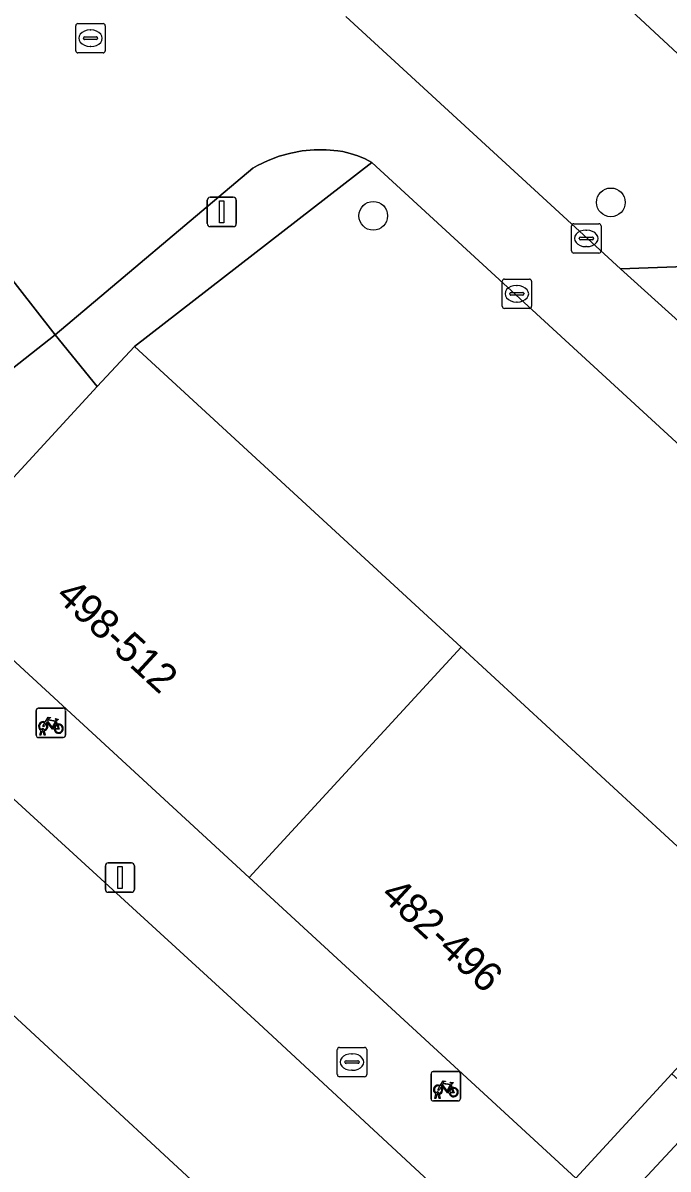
# Model space of a CAD drawing. Extents: x 159217 to 160349, y 381246 to 382172.
# Drawn here: x 159638.89 to 159660.85, y 381556.67 to 381595.69 of the extents above; entities that cross this region are included whole.
import ezdxf

# ---------------------------------------------------------------- set-up
doc = ezdxf.new("R2010")
doc.units = 0
for name, color, linetype in [('IMGEO_Boom', 7, 'Continuous'), ('IMGEO_Brandkraan', 7, 'Continuous'), ('IMGEO_Fietsenrek', 7, 'Continuous'), ('IMGEO_Groenvoorziening', 7, 'Continuous'), ('IMGEO_Kolk', 7, 'Continuous'), ('IMGEO_Lichtmast', 7, 'Continuous'), ('IMGEO_Pand', 7, 'Continuous'), ('IMGEO_Pand_nummerreeks', 7, 'Continuous'), ('IMGEO_Parkeervlak_open', 7, 'Continuous'), ('IMGEO_Rijbaan_lokaal_open', 7, 'Continuous'), ('IMGEO_Voetpad_open', 7, 'Continuous')]:
    doc.layers.add(name, color=color, linetype=linetype)

msp = doc.modelspace()

# ---------------------------------------------------------------- linework, layer by layer
at = {"layer": 'IMGEO_Boom'}
for centre in [(159658.907, 381589.584), (159650.817, 381589.128)]:
    msp.add_circle(centre, 0.489, dxfattribs=at)
at = {"layer": 'IMGEO_Brandkraan'}
for p, q in [((159649.594, 381559.889), (159649.594, 381560.741)), ((159649.669, 381560.815), (159650.521, 381560.815)), ((159650.082, 381560.595), (159650.107, 381560.595)), ((159650.595, 381560.741), (159650.595, 381559.889)), ((159649.853, 381560.309), (159649.853, 381560.321)), ((159650.291, 381560.272), (159649.893, 381560.272)), ((159649.896, 381560.358), (159650.294, 381560.358)), ((159650.337, 381560.321), (159650.337, 381560.309)), ((159650.521, 381559.815), (159649.669, 381559.815)), ((159650.105, 381560.035), (159650.08, 381560.035))]:
    msp.add_line(p, q, dxfattribs=at)
for points in [[(159649.594, 381559.889), (159649.594, 381560.741)], [(159649.669, 381560.815), (159650.521, 381560.815)], [(159650.595, 381560.741), (159650.595, 381559.889)], [(159650.521, 381559.815), (159649.669, 381559.815)]]:
    msp.add_lwpolyline(points, dxfattribs=at)
for centre, radius, start, end in [((159649.671, 381560.739), 0.0765, 91.552, 178.448), ((159649.671, 381560.739), 0.0765, 91.552, 178.448), ((159650.519, 381560.739), 0.0765, 1.552, 88.448), ((159650.519, 381560.739), 0.0765, 1.552, 88.448), ((159649.893, 381560.318), 0.0403, 85.8775, 175.7526), ((159649.89, 381560.308), 0.0366, 178.938, 274.7102), ((159650.294, 381560.315), 0.043, 264.8664, 352.4533), ((159650.298, 381560.32), 0.0386, 1.7309, 96.639), ((159649.671, 381559.891), 0.0765, 181.552, 268.448), ((159649.671, 381559.891), 0.0765, 181.552, 268.448), ((159650.519, 381559.891), 0.0765, 271.552, 358.448), ((159650.519, 381559.891), 0.0765, 271.552, 358.448)]:
    msp.add_arc(centre, radius, start, end, dxfattribs=at)
for centre, major_axis, ratio, start_param, end_param in [((159650.081, 381560.315), (-0.387, 0.002), 0.722429, 4.712389, 7.853982), ((159650.106, 381560.315), (-0.39, 0.002), 0.717154, 1.570796, 4.712389)]:
    msp.add_ellipse(centre, major_axis=major_axis, ratio=ratio, start_param=start_param, end_param=end_param, dxfattribs=at)
at = {"layer": 'IMGEO_Fietsenrek'}
for p, q in [((159639.341, 381571.44), (159639.341, 381572.281)), ((159639.341, 381572.281), (159639.341, 381571.44)), ((159639.416, 381572.365), (159640.257, 381572.365)), ((159640.257, 381572.365), (159639.416, 381572.365)), ((159640.341, 381572.29), (159640.341, 381571.449)), ((159640.341, 381571.449), (159640.341, 381572.29)), ((159640.028, 381571.914), (159640.064, 381571.819)), ((159640.266, 381571.365), (159639.425, 381571.365)), ((159639.425, 381571.365), (159640.266, 381571.365)), ((159639.468, 381571.449), (159639.507, 381571.609)), ((159639.502, 381571.449), (159639.468, 381571.449)), ((159639.537, 381571.597), (159639.502, 381571.449)), ((159639.579, 381571.621), (159639.578, 381571.625)), ((159639.62, 381571.449), (159639.586, 381571.591)), ((159639.61, 381571.632), (159639.611, 381571.625)), ((159639.618, 381571.595), (159639.653, 381571.449)), ((159639.653, 381571.449), (159639.62, 381571.449)), ((159652.785, 381559.065), (159652.785, 381559.906)), ((159652.785, 381559.906), (159652.785, 381559.065)), ((159652.86, 381559.99), (159653.701, 381559.99)), ((159653.701, 381559.99), (159652.86, 381559.99)), ((159653.785, 381559.915), (159653.785, 381559.074)), ((159653.785, 381559.074), (159653.785, 381559.915)), ((159653.472, 381559.539), (159653.508, 381559.444)), ((159653.71, 381558.99), (159652.869, 381558.99)), ((159652.869, 381558.99), (159653.71, 381558.99)), ((159652.912, 381559.074), (159652.951, 381559.234)), ((159652.946, 381559.074), (159652.912, 381559.074)), ((159652.981, 381559.222), (159652.946, 381559.074)), ((159653.023, 381559.246), (159653.022, 381559.25)), ((159653.064, 381559.074), (159653.03, 381559.216)), ((159653.054, 381559.257), (159653.055, 381559.25)), ((159653.062, 381559.22), (159653.097, 381559.074)), ((159653.097, 381559.074), (159653.064, 381559.074))]:
    msp.add_line(p, q, dxfattribs=at)
for points in [[(159639.675, 381571.839), (159639.623, 381571.749), (159639.583, 381571.724), (159639.584, 381571.771), (159639.639, 381571.865)], [(159639.654, 381571.891), (159639.749, 381572.055), (159639.835, 381572.041), (159639.837, 381572.032), (159639.781, 381572.021), (159639.754, 381571.976), (159640.01, 381571.935)], [(159639.95, 381571.647), (159639.9, 381571.647), (159639.709, 381571.898), (159639.69, 381571.866)], [(159639.997, 381571.91), (159639.74, 381571.951), (159639.723, 381571.922), (159639.89, 381571.702), (159639.997, 381571.91)], [(159640.045, 381571.812), (159640.015, 381571.889), (159639.906, 381571.671), (159639.949, 381571.671)], [(159639.979, 381571.671), (159640.099, 381571.67), (159640.055, 381571.784)], [(159640.075, 381571.791), (159640.13, 381571.646), (159639.98, 381571.646)], [(159640.01, 381571.935), (159640.035, 381571.984), (159640.029, 381571.988), (159640.006, 381571.992), (159639.994, 381571.999), (159639.993, 381572.002), (159639.995, 381572.007), (159640.09, 381571.992), (159640.092, 381571.982), (159640.082, 381571.969), (159640.07, 381571.963), (159640.056, 381571.969), (159640.028, 381571.914)], [(159653.098, 381559.516), (159653.193, 381559.68), (159653.279, 381559.666), (159653.281, 381559.657), (159653.225, 381559.646), (159653.198, 381559.601), (159653.454, 381559.56)], [(159653.119, 381559.464), (159653.067, 381559.374), (159653.027, 381559.349), (159653.028, 381559.396), (159653.083, 381559.49)], [(159653.394, 381559.272), (159653.344, 381559.272), (159653.153, 381559.523), (159653.134, 381559.491)], [(159653.441, 381559.535), (159653.184, 381559.576), (159653.167, 381559.547), (159653.334, 381559.327), (159653.441, 381559.535)], [(159653.489, 381559.437), (159653.459, 381559.514), (159653.35, 381559.296), (159653.393, 381559.296)], [(159653.423, 381559.296), (159653.543, 381559.295), (159653.499, 381559.409)], [(159653.519, 381559.416), (159653.574, 381559.271), (159653.424, 381559.271)], [(159653.454, 381559.56), (159653.479, 381559.609), (159653.473, 381559.613), (159653.45, 381559.617), (159653.438, 381559.624), (159653.437, 381559.627), (159653.439, 381559.632), (159653.534, 381559.617), (159653.536, 381559.607), (159653.526, 381559.594), (159653.514, 381559.588), (159653.5, 381559.594), (159653.472, 381559.539)]]:
    msp.add_lwpolyline(points, dxfattribs=at)
for centre, radius, start, end in [((159639.419, 381572.287), 0.0779, 92.4484, 184.2845), ((159639.419, 381572.287), 0.0779, 92.4484, 184.2845), ((159640.263, 381572.287), 0.0779, 2.4484, 94.2845), ((159640.263, 381572.287), 0.0779, 2.4484, 94.2845), ((159639.581, 381571.75), 0.159, 62.6766, 242.1369), ((159639.581, 381571.75), 0.129, 63.3192, 238.903), ((159639.581, 381571.75), 0.129, 283.6043, 43.4302), ((159639.581, 381571.75), 0.159, 283.5766, 46.6042), ((159640.108, 381571.666), 0.159, 113.3408, 178.3217), ((159640.108, 381571.666), 0.159, 187.0065, 105.7708), ((159640.108, 381571.666), 0.129, 113.923, 177.9556), ((159640.108, 381571.666), 0.129, 188.6715, 104.5883), ((159639.419, 381571.443), 0.0779, 182.4484, 274.2845), ((159639.419, 381571.443), 0.0779, 182.4484, 274.2845), ((159639.561, 381571.621), 0.0499, 12.8025, 158.6934), ((159639.581, 381571.75), 0.159, 253.9967, 271.7867), ((159639.561, 381571.621), 0.0174, 12.8025, 163.4502), ((159639.581, 381571.75), 0.129, 253.415, 269.0204), ((159640.263, 381571.443), 0.0779, 272.4484, 4.2845), ((159640.263, 381571.443), 0.0779, 272.4484, 4.2845), ((159652.863, 381559.912), 0.0779, 92.4484, 184.2845), ((159652.863, 381559.912), 0.0779, 92.4484, 184.2845), ((159653.707, 381559.912), 0.0779, 2.4484, 94.2845), ((159653.707, 381559.912), 0.0779, 2.4484, 94.2845), ((159653.025, 381559.375), 0.159, 62.6766, 242.1369), ((159653.025, 381559.375), 0.129, 63.3192, 238.903), ((159653.005, 381559.246), 0.0499, 12.8025, 158.6934), ((159653.005, 381559.246), 0.0174, 12.8025, 163.4502), ((159653.025, 381559.375), 0.129, 283.6043, 43.4302), ((159653.025, 381559.375), 0.159, 283.5766, 46.6042), ((159653.552, 381559.291), 0.159, 113.3408, 178.3217), ((159653.552, 381559.291), 0.159, 187.0065, 105.7708), ((159653.552, 381559.291), 0.129, 113.923, 177.9556), ((159653.552, 381559.291), 0.129, 188.6715, 104.5883), ((159652.863, 381559.068), 0.0779, 182.4484, 274.2845), ((159652.863, 381559.068), 0.0779, 182.4484, 274.2845), ((159653.025, 381559.375), 0.159, 253.9967, 271.7867), ((159653.025, 381559.375), 0.129, 253.415, 269.0204), ((159653.707, 381559.068), 0.0779, 272.4484, 4.2845), ((159653.707, 381559.068), 0.0779, 272.4484, 4.2845)]:
    msp.add_arc(centre, radius, start, end, dxfattribs=at)
at = {"layer": 'IMGEO_Groenvoorziening'}
msp.add_lwpolyline([(159692.005, 381604.643), (159690.074, 381606.457), (159682.249, 381613.809), (159680.462, 381615.488), (159678.112, 381617.696), (159666.889, 381608.847), (159664.757, 381607.166), (159661.453, 381604.561), (159655.531, 381599.891), (159667.442, 381588.844), (159673.929, 381582.827), (159675.769, 381581.12), (159687.565, 381570.179), (159706.244, 381585.938), (159705.893, 381586.316), (159707.664, 381587.959), (159708.044, 381587.55), (159709.165, 381588.521), (159704.338, 381593.056)], close=True, dxfattribs=at)
for points in [[(159649.883, 381595.917), (159652.392, 381593.608), (159653.239, 381592.829), (159659.239, 381587.321), (159666.781, 381587.598), (159666.437, 381587.895), (159667.442, 381588.844), (159655.531, 381599.891)], [(159650.773, 381590.94), (159642.684, 381584.683), (159653.807, 381574.44), (159664.922, 381564.205), (159663.33, 381562.473), (159665.149, 381560.892), (159665.707, 381560.407), (159663.314, 381557.831), (159662.858, 381558.237), (159662.123, 381557.38), (159661.529, 381557.926), (159658.33, 381554.491), (159662.979, 381550.231), (159679.309, 381562.818)], [(159677.507, 381566.366), (159650.773, 381590.94)]]:
    msp.add_lwpolyline(points, dxfattribs=at)
at = {"layer": 'IMGEO_Kolk'}
for p, q in [((159640.691, 381594.748), (159640.691, 381595.6)), ((159640.766, 381595.674), (159641.618, 381595.674)), ((159641.692, 381595.6), (159641.692, 381594.748)), ((159640.95, 381595.168), (159640.95, 381595.18)), ((159640.993, 381595.217), (159641.391, 381595.217)), ((159641.179, 381595.454), (159641.204, 381595.454)), ((159641.434, 381595.18), (159641.434, 381595.168)), ((159641.388, 381595.131), (159640.99, 381595.131)), ((159641.202, 381594.894), (159641.177, 381594.894)), ((159641.618, 381594.674), (159640.766, 381594.674)), ((159657.571, 381587.931), (159657.571, 381588.783)), ((159657.646, 381588.857), (159658.498, 381588.857)), ((159658.059, 381588.637), (159658.084, 381588.637)), ((159658.572, 381588.783), (159658.572, 381587.931)), ((159657.83, 381588.351), (159657.83, 381588.363)), ((159658.268, 381588.314), (159657.87, 381588.314)), ((159657.873, 381588.4), (159658.271, 381588.4)), ((159658.314, 381588.363), (159658.314, 381588.351)), ((159658.498, 381587.857), (159657.646, 381587.857)), ((159658.082, 381588.077), (159658.057, 381588.077)), ((159655.281, 381586.972), (159656.133, 381586.972)), ((159655.206, 381586.046), (159655.206, 381586.898)), ((159655.694, 381586.752), (159655.719, 381586.752)), ((159656.207, 381586.898), (159656.207, 381586.046)), ((159655.465, 381586.466), (159655.465, 381586.478)), ((159655.903, 381586.429), (159655.505, 381586.429)), ((159655.508, 381586.515), (159655.906, 381586.515)), ((159655.717, 381586.192), (159655.692, 381586.192)), ((159655.949, 381586.478), (159655.949, 381586.466)), ((159656.133, 381585.972), (159655.281, 381585.972))]:
    msp.add_line(p, q, dxfattribs=at)
for points in [[(159640.691, 381594.748), (159640.691, 381595.6)], [(159640.766, 381595.674), (159641.618, 381595.674)], [(159641.692, 381595.6), (159641.692, 381594.748)], [(159641.618, 381594.674), (159640.766, 381594.674)], [(159657.571, 381587.931), (159657.571, 381588.783)], [(159657.646, 381588.857), (159658.498, 381588.857)], [(159658.572, 381588.783), (159658.572, 381587.931)], [(159658.498, 381587.857), (159657.646, 381587.857)], [(159655.281, 381586.972), (159656.133, 381586.972)], [(159655.206, 381586.046), (159655.206, 381586.898)], [(159656.207, 381586.898), (159656.207, 381586.046)], [(159656.133, 381585.972), (159655.281, 381585.972)]]:
    msp.add_lwpolyline(points, dxfattribs=at)
for centre, radius, start, end in [((159640.768, 381595.598), 0.0765, 91.552, 178.448), ((159640.768, 381595.598), 0.0765, 91.552, 178.448), ((159641.616, 381595.598), 0.0765, 1.552, 88.448), ((159641.616, 381595.598), 0.0765, 1.552, 88.448), ((159640.99, 381595.177), 0.0403, 85.8775, 175.7526), ((159640.987, 381595.167), 0.0366, 178.938, 274.7102), ((159641.391, 381595.174), 0.043, 264.8664, 352.4533), ((159641.395, 381595.179), 0.0386, 1.7309, 96.639), ((159640.768, 381594.75), 0.0765, 181.552, 268.448), ((159640.768, 381594.75), 0.0765, 181.552, 268.448), ((159641.616, 381594.75), 0.0765, 271.552, 358.448), ((159641.616, 381594.75), 0.0765, 271.552, 358.448), ((159657.648, 381588.781), 0.0765, 91.552, 178.448), ((159657.648, 381588.781), 0.0765, 91.552, 178.448), ((159658.496, 381588.781), 0.0765, 1.552, 88.448), ((159658.496, 381588.781), 0.0765, 1.552, 88.448), ((159657.87, 381588.36), 0.0403, 85.8775, 175.7526), ((159657.867, 381588.35), 0.0366, 178.938, 274.7102), ((159658.271, 381588.357), 0.043, 264.8664, 352.4533), ((159658.275, 381588.362), 0.0386, 1.7309, 96.639), ((159657.648, 381587.933), 0.0765, 181.552, 268.448), ((159657.648, 381587.933), 0.0765, 181.552, 268.448), ((159658.496, 381587.933), 0.0765, 271.552, 358.448), ((159658.496, 381587.933), 0.0765, 271.552, 358.448), ((159655.283, 381586.896), 0.0765, 91.552, 178.448), ((159655.283, 381586.896), 0.0765, 91.552, 178.448), ((159656.131, 381586.896), 0.0765, 1.552, 88.448), ((159656.131, 381586.896), 0.0765, 1.552, 88.448), ((159655.505, 381586.475), 0.0403, 85.8775, 175.7526), ((159655.502, 381586.465), 0.0366, 178.938, 274.7102), ((159655.906, 381586.472), 0.043, 264.8664, 352.4533), ((159655.91, 381586.477), 0.0386, 1.7309, 96.639), ((159655.283, 381586.048), 0.0765, 181.552, 268.448), ((159655.283, 381586.048), 0.0765, 181.552, 268.448), ((159656.131, 381586.048), 0.0765, 271.552, 358.448), ((159656.131, 381586.048), 0.0765, 271.552, 358.448)]:
    msp.add_arc(centre, radius, start, end, dxfattribs=at)
for centre, major_axis, ratio, start_param, end_param in [((159641.178, 381595.174), (-0.387, 0.002), 0.722429, 4.712389, 7.853982), ((159641.203, 381595.174), (-0.39, 0.002), 0.717154, 1.570796, 4.712389), ((159658.058, 381588.357), (-0.387, 0.002), 0.722429, 4.712389, 7.853982), ((159658.083, 381588.357), (-0.39, 0.002), 0.717154, 1.570796, 4.712389), ((159655.693, 381586.472), (-0.387, 0.002), 0.722429, 4.712389, 7.853982), ((159655.718, 381586.472), (-0.39, 0.002), 0.717154, 1.570796, 4.712389)]:
    msp.add_ellipse(centre, major_axis=major_axis, ratio=ratio, start_param=start_param, end_param=end_param, dxfattribs=at)
at = {"layer": 'IMGEO_Lichtmast'}
for p, q in [((159645.264, 381589.76), (159646.054, 381589.76)), ((159646.054, 381589.76), (159645.264, 381589.76)), ((159645.164, 381588.86), (159645.164, 381589.66)), ((159645.164, 381589.66), (159645.164, 381588.86)), ((159646.154, 381589.66), (159646.154, 381588.86)), ((159646.154, 381588.86), (159646.154, 381589.66)), ((159646.054, 381588.76), (159645.264, 381588.76)), ((159645.264, 381588.76), (159646.054, 381588.76)), ((159641.797, 381567.094), (159642.587, 381567.094)), ((159642.587, 381567.094), (159641.797, 381567.094)), ((159641.697, 381566.194), (159641.697, 381566.994)), ((159641.697, 381566.994), (159641.697, 381566.194)), ((159642.687, 381566.994), (159642.687, 381566.194)), ((159642.687, 381566.194), (159642.687, 381566.994)), ((159642.587, 381566.094), (159641.797, 381566.094)), ((159641.797, 381566.094), (159642.587, 381566.094))]:
    msp.add_line(p, q, dxfattribs=at)
for points in [[(159645.584, 381589.635), (159645.734, 381589.635), (159645.734, 381588.885), (159645.584, 381588.885), (159645.584, 381589.635)], [(159642.117, 381566.969), (159642.267, 381566.969), (159642.267, 381566.219), (159642.117, 381566.219), (159642.117, 381566.969)]]:
    msp.add_lwpolyline(points, dxfattribs=at)
for centre, start, end in [((159645.264, 381589.66), 90, 180), ((159645.264, 381589.66), 90, 180), ((159646.054, 381589.66), 0, 90), ((159646.054, 381589.66), 360, 90), ((159645.264, 381588.86), 180, 270), ((159645.264, 381588.86), 180, 270), ((159646.054, 381588.86), 270, 0), ((159646.054, 381588.86), 270, 0), ((159641.797, 381566.994), 90, 180), ((159641.797, 381566.994), 90, 180), ((159642.587, 381566.994), 0, 90), ((159642.587, 381566.994), 360, 90), ((159641.797, 381566.194), 180, 270), ((159641.797, 381566.194), 180, 270), ((159642.587, 381566.194), 270, 0), ((159642.587, 381566.194), 270, 0)]:
    msp.add_arc(centre, 0.1, start, end, dxfattribs=at)
at = {"layer": 'IMGEO_Pand'}
for points in [[(159638.093, 381587.494), (159633.188, 381583.639), (159635.089, 381581.22), (159639.994, 381585.075)], [(159646.591, 381566.603), (159653.807, 381574.44), (159642.684, 381584.683), (159641.423, 381583.314), (159635.465, 381576.844)], [(159653.807, 381574.44), (159646.591, 381566.603), (159657.716, 381556.362), (159660.977, 381559.912), (159663.33, 381562.473), (159664.922, 381564.205)]]:
    msp.add_lwpolyline(points, close=True, dxfattribs=at)
at = {"layer": 'IMGEO_Parkeervlak_open'}
for points in [[(159674.834, 381580.112), (159672.995, 381581.822), (159666.781, 381587.598), (159659.239, 381587.321), (159679.193, 381569.297), (159686.25, 381569.501)], [(159633.826, 381566.283), (159626.336, 381565.999), (159636.471, 381556.609), (159638.412, 381554.81), (159644.093, 381549.547), (159651.593, 381549.847)]]:
    msp.add_lwpolyline(points, close=True, dxfattribs=at)
at = {"layer": 'IMGEO_Rijbaan_lokaal_open'}
for points in [[(159630.728, 381596.866), (159632.391, 381594.75), (159634.292, 381592.331), (159636.192, 381589.913), (159638.093, 381587.494), (159639.994, 381585.075), (159646.714, 381590.744), (159646.874, 381590.835), (159647.238, 381591.01), (159647.616, 381591.153), (159648.006, 381591.261), (159648.403, 381591.335), (159648.806, 381591.372), (159649.21, 381591.373), (159649.613, 381591.338), (159649.777, 381591.313), (159650.037, 381591.254), (159650.292, 381591.171), (159650.537, 381591.066), (159650.773, 381590.94), (159677.507, 381566.366)], [(159682.752, 381566.058), (159681.969, 381566.632), (159679.193, 381569.297), (159659.239, 381587.321), (159653.239, 381592.829), (159652.392, 381593.608), (159649.883, 381595.917)], [(159660.906, 381549.028), (159660.442, 381549.271), (159660.001, 381549.554), (159659.588, 381549.876), (159646.917, 381561.624), (159632.794, 381574.549), (159632.285, 381574.975), (159631.74, 381575.354), (159631.163, 381575.682), (159630.559, 381575.958), (159629.933, 381576.179), (159629.29, 381576.343), (159628.635, 381576.449), (159628.4, 381576.472), (159627.777, 381576.519), (159627.152, 381576.51), (159626.531, 381576.445), (159625.918, 381576.325), (159625.318, 381576.151), (159624.736, 381575.924), (159624.177, 381575.646), (159623.645, 381575.319), (159623.373, 381575.125), (159611.28, 381565.67)], [(159631.325, 381568.558), (159632.237, 381567.776), (159633.826, 381566.283), (159651.593, 381549.847), (159652.783, 381548.746), (159653.171, 381548.351), (159654.564, 381546.933), (159655.073, 381546.237)]]:
    msp.add_lwpolyline(points, dxfattribs=at)
at = {"layer": 'IMGEO_Voetpad_open'}
msp.add_lwpolyline([(159650.773, 381590.94), (159650.537, 381591.066), (159650.292, 381591.171), (159650.037, 381591.254), (159649.777, 381591.313), (159649.613, 381591.338), (159649.21, 381591.373), (159648.806, 381591.372), (159648.403, 381591.335), (159648.006, 381591.261), (159647.616, 381591.153), (159647.238, 381591.01), (159646.874, 381590.835), (159646.714, 381590.744), (159639.994, 381585.075), (159641.423, 381583.314), (159642.684, 381584.683)], close=True, dxfattribs=at)
for points in [[(159641.423, 381583.314), (159639.994, 381585.075), (159635.089, 381581.22), (159633.188, 381583.639), (159631.368, 381585.955), (159619.451, 381576.59), (159607.656, 381567.322), (159595.862, 381558.054), (159584.068, 381548.786), (159584.683, 381547.956), (159583.479, 381547.014), (159580.2, 381544.451), (159581.921, 381542.835)], [(159679.309, 381562.818), (159662.979, 381550.231), (159658.33, 381554.491), (159661.529, 381557.926), (159662.123, 381557.38), (159662.858, 381558.237), (159660.977, 381559.912), (159657.716, 381556.362), (159646.591, 381566.603), (159635.465, 381576.844), (159641.423, 381583.314)], [(159611.28, 381565.67), (159623.373, 381575.125), (159623.645, 381575.319), (159624.177, 381575.646), (159624.736, 381575.924), (159625.318, 381576.151), (159625.918, 381576.325), (159626.531, 381576.445), (159627.152, 381576.51), (159627.777, 381576.519), (159628.4, 381576.472), (159628.635, 381576.449), (159629.29, 381576.343), (159629.933, 381576.179), (159630.559, 381575.958), (159631.163, 381575.682), (159631.74, 381575.354), (159632.285, 381574.975), (159632.794, 381574.549), (159646.917, 381561.624), (159659.588, 381549.876), (159660.001, 381549.554), (159660.442, 381549.271), (159660.906, 381549.028)]]:
    msp.add_lwpolyline(points, dxfattribs=at)

# ---------------------------------------------------------------- texts
at = {"layer": 'IMGEO_Pand_nummerreeks'}
for s, rotation, p in [('498-512', 317.3705, (159639.965, 381576.127)), ('482-496', 317.3719, (159651.028, 381565.944))]:
    msp.add_text(s, height=1, rotation=rotation, dxfattribs=at).set_placement(p)

doc.saveas('drawing.dxf')
